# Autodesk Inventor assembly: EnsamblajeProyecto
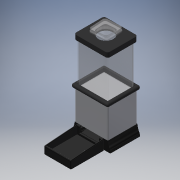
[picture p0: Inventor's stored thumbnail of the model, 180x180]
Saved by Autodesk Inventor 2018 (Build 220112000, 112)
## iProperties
Created: 2022-01
Part Number: EnsamblajeProyecto
Document SubType Name: Assembly
Designer: Asus
Author: Asus
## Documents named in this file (8)
- C:\Users\Asus\Documents\Inventor\PoryectoSE\EnsamblajeProyecto.iam
- C:\Users\Asus\Documents\Inventor\PoryectoSE\Base.ipt
- C:\Users\Asus\Documents\Inventor\PoryectoSE\Plato.ipt
- C:\Users\Asus\Documents\Inventor\PoryectoSE\Panel.ipt
- C:\Users\Asus\Documents\Inventor\PoryectoSE\Union.ipt
- C:\Users\Asus\Documents\Inventor\PoryectoSE\Contenedor.ipt
- C:\Users\Asus\Documents\Inventor\PoryectoSE\Tapa.ipt
- C:\Users\Asus\Documents\Inventor\PoryectoSE\Tapon.ipt
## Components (7 placed, 7 different names)
1. Base:1 — Coincidencia:1, Coincidencia:2, Nivelación:2
2. Plato:1 — Coincidencia:1
3. Panel:1 — Coincidencia:2, Nivelación:2, Coincidencia:3, Ángulo:1, Coincidencia:4
4. Union:1 — Coincidencia:3, Ángulo:1, Coincidencia:5, Coincidencia:6
5. Contenedor:1 — Coincidencia:4, Coincidencia:5, Coincidencia:6, Coincidencia:7, Coincidencia:9
6. Tapa:1 — Coincidencia:7, Coincidencia:9, Insertar:1
7. Tapon:1 — Insertar:1
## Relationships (11: Mate 8, Flush 1, Angle 1, Insert 1)
- Coincidencia:1 [Mate]: Base:1 ↔ Plato:1
- Coincidencia:2 [Mate]: Base:1 ↔ Panel:1
- Nivelación:2 [Flush]: Base:1 ↔ Panel:1
- Coincidencia:3 [Mate]: Panel:1 ↔ Union:1
- Ángulo:1 [Angle]: Panel:1 ↔ Union:1
- Coincidencia:4 [Mate]: Panel:1 ↔ Contenedor:1
- Coincidencia:5 [Mate]: Union:1 ↔ Contenedor:1
- Coincidencia:6 [Mate]: Union:1 ↔ Contenedor:1
- Coincidencia:7 [Mate]: Contenedor:1 ↔ Tapa:1
- Coincidencia:9 [Mate]: Contenedor:1 ↔ Tapa:1
- Insertar:1: Tapa:1 ↔ Tapon:1
